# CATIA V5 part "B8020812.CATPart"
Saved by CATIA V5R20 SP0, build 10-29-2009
Part number: B8020812
Revision: 4
Definition: design
Nomenclature: B8020812
Source: made
Description: NOT SPECIFIED
Bounding box of the stored display mesh (mm): x -10.5 to 10.5, y -10.5 to 10.5, z -6 to 12
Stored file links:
  C:\Users\Utente\Desktop\3D files B802\B8020812.CATPart
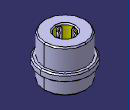
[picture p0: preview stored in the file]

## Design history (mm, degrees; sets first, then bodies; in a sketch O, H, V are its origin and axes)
Body1 "MANIFOLD_SOLID_BREP #38" (main body)
  Solid1: solid without history
Body2 "MANIFOLD_SOLID_BREP #76"
  Solid2: solid without history
Body3 "MANIFOLD_SOLID_BREP #114"
  Solid3: solid without history
Body4 "MANIFOLD_SOLID_BREP #152"
  Solid4: solid without history
Body5 "MANIFOLD_SOLID_BREP #190"
  Solid5: solid without history
Body6 "MANIFOLD_SOLID_BREP #228"
  Solid6: solid without history
Body7 "MANIFOLD_SOLID_BREP #266"
  Solid7: solid without history
Body8 "MANIFOLD_SOLID_BREP #1728"
  Solid8: solid without history
Body9 "MANIFOLD_SOLID_BREP #1766"
  Solid9: solid without history
Body10 "MANIFOLD_SOLID_BREP #1804"
  Solid10: solid without history
Body11 "MANIFOLD_SOLID_BREP #1842"
  Solid11: solid without history
Body12 "MANIFOLD_SOLID_BREP #1880"
  Solid12: solid without history
Body13 "MANIFOLD_SOLID_BREP #1918"
  Solid13: solid without history
Body14 "MANIFOLD_SOLID_BREP #1956"
  Solid14: solid without history
Body15 "MANIFOLD_SOLID_BREP #1994"
  Solid15: solid without history
Body16 "MANIFOLD_SOLID_BREP #2032"
  Solid16: solid without history
Body17 "MANIFOLD_SOLID_BREP #2070"
  Solid17: solid without history
Body18 "MANIFOLD_SOLID_BREP #2108"
  Solid18: solid without history
Body19 "MANIFOLD_SOLID_BREP #2146"
  Solid19: solid without history
Body20 "MANIFOLD_SOLID_BREP #2184"
  Solid20: solid without history
Body21 "MANIFOLD_SOLID_BREP #2222"
  Solid21: solid without history
Body22 "MANIFOLD_SOLID_BREP #2260"
  Solid22: solid without history
Body23 "MANIFOLD_SOLID_BREP #2298"
  Solid23: solid without history
Body24 "MANIFOLD_SOLID_BREP #2336"
  Solid24: solid without history
Body25 "MANIFOLD_SOLID_BREP #2374"
  Solid25: solid without history
Body26 "MANIFOLD_SOLID_BREP #2412"
  Solid26: solid without history
Body27 "MANIFOLD_SOLID_BREP #2450"
  Solid27: solid without history
Body28 "MANIFOLD_SOLID_BREP #2488"
  Solid28: solid without history
Body29 "MANIFOLD_SOLID_BREP #2526"
  Solid29: solid without history
Body30 "MANIFOLD_SOLID_BREP #2564"
  Solid30: solid without history
Body31 "MANIFOLD_SOLID_BREP #2602"
  Solid31: solid without history
Body32 "MANIFOLD_SOLID_BREP #2640"
  Solid32: solid without history
Body33 "MANIFOLD_SOLID_BREP #2678"
  Solid33: solid without history
Body34 "MANIFOLD_SOLID_BREP #2716"
  Solid34: solid without history
Body35 "MANIFOLD_SOLID_BREP #2754"
  Solid35: solid without history
Body36 "MANIFOLD_SOLID_BREP #2792"
  Solid36: solid without history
